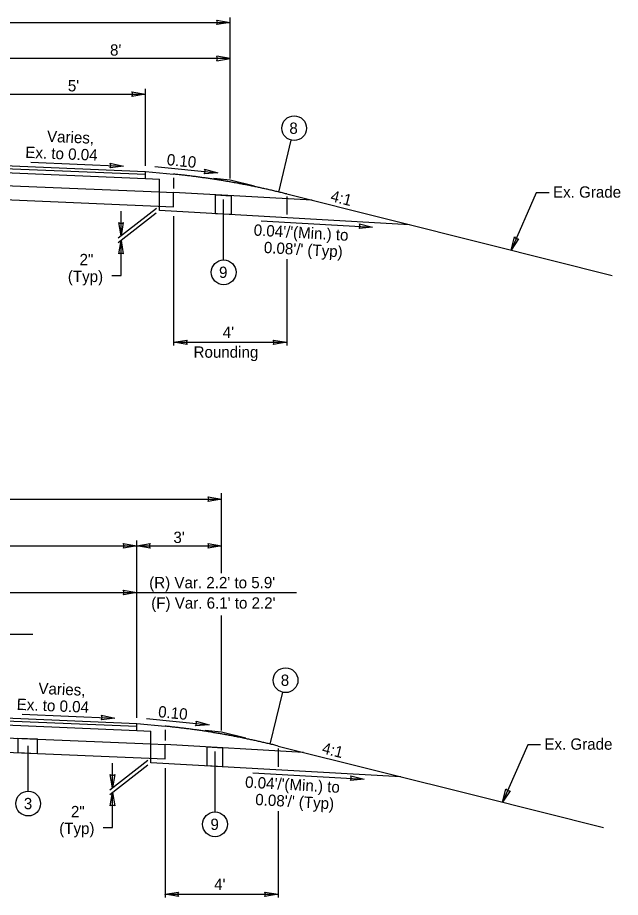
# Model space of a CAD drawing. Extents: x -219 to 803, y -225 to 180.
# Drawn here: x -126.41 to -105.09, y -38.66 to -7.57 of the extents above; entities that cross this region are included whole.
import ezdxf

# ---------------------------------------------------------------- set-up
doc = ezdxf.new("R2010")
doc.units = 0
doc.layers.add('Level 16', color=7, linetype='Continuous')
doc.layers.add('XS_X_Pavt', color=7, linetype='Continuous')

msp = doc.modelspace()

# ---------------------------------------------------------------- linework, layer by layer
at = {"layer": 'Level 16'}
for p, q in [((-137.894, -7.736), (-118.894, -7.736)), ((-119.368, -7.657), (-118.894, -7.736)), ((-118.894, -7.736), (-119.367, -7.815)), ((-118.894, -13.251), (-118.894, -7.566)), ((-119.367, -7.815), (-119.367, -7.815)), ((-118.894, -9.014), (-126.894, -9.014)), ((-119.368, -9.093), (-118.894, -9.014)), ((-118.894, -9.014), (-119.367, -8.935)), ((-119.367, -8.935), (-119.367, -8.935)), ((-122.369, -10.195), (-121.894, -10.274)), ((-121.894, -12.808), (-121.894, -10.078)), ((-126.894, -10.274), (-121.894, -10.274)), ((-121.894, -10.274), (-122.367, -10.353)), ((-122.367, -10.353), (-122.367, -10.353)), ((-117.17, -13.732), (-116.732, -11.9)), ((-125.947, -12.678), (-122.668, -12.815)), ((-123.139, -12.716), (-122.668, -12.815)), ((-126.894, -12.792), (-121.894, -13)), ((-126.894, -12.896), (-121.894, -13.104)), ((-126.892, -13.042), (-121.894, -13.25)), ((-122.668, -12.815), (-123.144, -12.874)), ((-123.144, -12.874), (-123.144, -12.874)), ((-121.894, -13.25), (-121.894, -13)), ((-121.894, -13), (-120.894, -13.1)), ((-121.554, -12.83), (-119.333, -13.052)), ((-119.333, -13.052), (-119.812, -13.084)), ((-119.798, -12.926), (-119.333, -13.052)), ((-121.894, -13.25), (-121.394, -13.271)), ((-121.394, -13.729), (-121.394, -13.271)), ((-120.894, -13.228), (-120.894, -13.603)), ((-119.812, -13.084), (-119.812, -13.084)), ((-119.469, -13.242), (-118.894, -13.3)), ((-118.894, -13.3), (-118.029, -13.516)), ((-126.889, -13.5), (-121.394, -13.729)), ((-121.394, -13.729), (-120.894, -13.75)), ((-121.394, -14.229), (-121.394, -13.729)), ((-120.894, -14.25), (-120.894, -13.75)), ((-115.997, -14.024), (-120.894, -13.75)), ((-119.124, -16.13), (-119.124, -13.992)), ((-116.894, -13.8), (-109.797, -15.574)), ((-116.894, -13.885), (-116.894, -14.531)), ((-108.066, -13.763), (-108.956, -15.784)), ((-107.615, -13.763), (-108.066, -13.763)), ((-126.886, -14), (-120.894, -14.25)), ((-121.394, -14.39), (-121.394, -14.223)), ((-121.506, -14.477), (-122.852, -15.522)), ((-121.5, -14.312), (-122.85, -15.36)), ((-122.752, -15.283), (-122.752, -14.409)), ((-112.555, -14.885), (-121.394, -14.39)), ((-120.894, -14.585), (-120.894, -19.151)), ((-122.752, -15.283), (-122.831, -14.81)), ((-122.831, -14.81), (-122.831, -14.81)), ((-122.673, -14.809), (-122.752, -15.283)), ((-117.793, -14.75), (-113.854, -14.971)), ((-114.323, -14.859), (-113.854, -14.971)), ((-113.854, -14.971), (-114.332, -15.017)), ((-114.332, -15.017), (-114.332, -15.017)), ((-122.831, -15.919), (-122.752, -15.444)), ((-122.752, -16.68), (-122.752, -15.444)), ((-122.752, -15.444), (-122.673, -15.917)), ((-108.956, -15.784), (-108.836, -15.32)), ((-108.691, -15.383), (-108.956, -15.784)), ((-108.836, -15.32), (-108.836, -15.32)), ((-109.797, -15.574), (-105.379, -16.679)), ((-122.673, -15.917), (-122.673, -15.917)), ((-116.894, -16.103), (-116.894, -19.151)), ((-123.081, -16.68), (-122.752, -16.68)), ((-120.894, -19.042), (-120.42, -18.963)), ((-120.42, -18.963), (-120.42, -18.963)), ((-117.369, -18.963), (-116.894, -19.042)), ((-120.419, -19.121), (-120.894, -19.042)), ((-120.894, -19.042), (-116.894, -19.042)), ((-116.894, -19.042), (-117.367, -19.121)), ((-117.367, -19.121), (-117.367, -19.121)), ((-119.673, -24.508), (-119.198, -24.587)), ((-119.198, -27.198), (-119.198, -24.373)), ((-138.198, -24.587), (-119.198, -24.587)), ((-119.198, -24.587), (-119.671, -24.666)), ((-119.671, -24.666), (-119.671, -24.666)), ((-122.198, -32.32), (-122.198, -26.047)), ((-138.198, -26.237), (-122.198, -26.237)), ((-122.673, -26.158), (-122.198, -26.237)), ((-122.198, -26.237), (-122.671, -26.316)), ((-122.671, -26.316), (-122.671, -26.316)), ((-122.198, -26.237), (-121.725, -26.158)), ((-121.723, -26.316), (-122.198, -26.237)), ((-122.198, -26.237), (-119.198, -26.237)), ((-121.725, -26.158), (-121.725, -26.158)), ((-119.673, -26.158), (-119.198, -26.237)), ((-119.198, -26.237), (-119.672, -26.316)), ((-119.672, -26.316), (-119.672, -26.316)), ((-127.198, -27.887), (-122.198, -27.887)), ((-122.673, -27.808), (-122.198, -27.887)), ((-122.198, -27.887), (-122.672, -27.966)), ((-122.672, -27.966), (-122.672, -27.966)), ((-122.198, -27.887), (-116.552, -27.887)), ((-119.198, -32.763), (-119.198, -28.695)), ((-126.998, -29.365), (-125.875, -29.365)), ((-117.475, -33.244), (-117.036, -31.412)), ((-127.198, -32.304), (-122.198, -32.512)), ((-126.252, -32.19), (-122.973, -32.327)), ((-122.973, -32.327), (-123.449, -32.386)), ((-123.444, -32.228), (-122.973, -32.327)), ((-127.198, -32.408), (-122.198, -32.616)), ((-127.196, -32.554), (-122.198, -32.762)), ((-123.449, -32.386), (-123.449, -32.386)), ((-122.198, -32.762), (-122.198, -32.512)), ((-122.198, -32.512), (-121.198, -32.612)), ((-121.858, -32.342), (-119.638, -32.564)), ((-119.638, -32.564), (-120.116, -32.596)), ((-120.116, -32.596), (-120.116, -32.596)), ((-120.102, -32.438), (-119.638, -32.564)), ((-122.198, -32.762), (-121.698, -32.783)), ((-121.698, -33.241), (-121.698, -32.783)), ((-121.198, -32.74), (-121.198, -33.115)), ((-119.773, -32.755), (-119.198, -32.812)), ((-119.198, -32.812), (-118.334, -33.028)), ((-127.193, -33.012), (-121.698, -33.241)), ((-125.709, -33.574), (-125.709, -33.074)), ((-121.698, -33.241), (-121.198, -33.262)), ((-121.698, -33.741), (-121.698, -33.241)), ((-121.198, -33.762), (-121.198, -33.262)), ((-116.301, -33.536), (-121.198, -33.262)), ((-127.191, -33.512), (-121.198, -33.762)), ((-126.409, -33.545), (-125.709, -33.574)), ((-126.038, -34.91), (-126.038, -33.303)), ((-119.429, -35.643), (-119.429, -33.504)), ((-117.198, -33.312), (-110.102, -35.086)), ((-117.198, -33.397), (-117.198, -34.043)), ((-108.37, -33.276), (-109.26, -35.296)), ((-107.92, -33.276), (-108.37, -33.276)), ((-121.804, -33.824), (-123.155, -34.872)), ((-121.698, -33.902), (-121.698, -33.735)), ((-121.811, -33.989), (-123.156, -35.034)), ((-123.056, -34.795), (-123.056, -33.921)), ((-112.859, -34.397), (-121.698, -33.902)), ((-121.198, -34.097), (-121.198, -38.663)), ((-123.056, -34.795), (-123.135, -34.322)), ((-123.135, -34.322), (-123.135, -34.322)), ((-122.977, -34.321), (-123.056, -34.795)), ((-118.097, -34.262), (-114.159, -34.483)), ((-114.159, -34.483), (-114.637, -34.529)), ((-114.627, -34.371), (-114.159, -34.483)), ((-114.637, -34.529), (-114.637, -34.529)), ((-123.135, -35.431), (-123.056, -34.956)), ((-123.056, -36.192), (-123.056, -34.956)), ((-123.056, -34.956), (-122.977, -35.429)), ((-110.102, -35.086), (-105.684, -36.191)), ((-109.26, -35.296), (-109.14, -34.832)), ((-108.995, -34.895), (-109.26, -35.296)), ((-109.14, -34.832), (-109.14, -34.832)), ((-122.977, -35.429), (-122.977, -35.429)), ((-117.198, -35.615), (-117.198, -38.663)), ((-123.386, -36.192), (-123.056, -36.192)), ((-121.198, -38.554), (-120.725, -38.475)), ((-120.723, -38.633), (-121.198, -38.554)), ((-121.198, -38.554), (-117.198, -38.554)), ((-120.725, -38.475), (-120.725, -38.475)), ((-117.673, -38.475), (-117.198, -38.554)), ((-117.198, -38.554), (-117.672, -38.633)), ((-117.672, -38.633), (-117.672, -38.633))]:
    msp.add_line(p, q, dxfattribs=at)
for points in [[(-119.407, -13.833), (-118.862, -13.864), (-118.862, -14.531), (-119.407, -14.501)], [(-119.711, -33.345), (-119.166, -33.376), (-119.166, -34.044), (-119.711, -34.013)]]:
    msp.add_lwpolyline(points, close=True, dxfattribs=at)
msp.add_lwpolyline([(-125.709, -33.074), (-126.409, -33.045), (-126.409, -33.545)], dxfattribs=at)
for centre in [(-116.63, -11.475), (-119.124, -16.568), (-116.934, -30.987), (-126.038, -35.347), (-119.429, -36.08)]:
    msp.add_circle(centre, 0.438, dxfattribs=at)
for centre, start, end in [((-119.488, -7.737), 327.1412, 33.822), ((-119.488, -9.013), 326.178, 32.8588), ((-122.488, -10.275), 327.1412, 33.822), ((-123.262, -12.791), 324.7553, 31.4361), ((-119.925, -12.994), 321.431, 28.1118), ((-122.753, -14.689), 237.1412, 303.822), ((-114.447, -14.931), 323.2284, 29.9091), ((-108.715, -15.241), 213.1754, 279.8561), ((-122.751, -16.038), 57.1412, 123.822), ((-120.299, -19.041), 147.1412, 213.822), ((-117.488, -19.043), 327.1412, 33.822), ((-119.793, -24.588), 327.1412, 33.822), ((-122.793, -26.238), 327.1412, 33.822), ((-121.604, -26.236), 147.1412, 213.822), ((-119.793, -26.238), 327.1412, 33.822), ((-122.793, -27.888), 327.1412, 33.822), ((-123.567, -32.303), 324.7553, 31.4361), ((-120.229, -32.506), 321.431, 28.1118), ((-123.057, -34.201), 237.1412, 303.822), ((-114.752, -34.443), 323.2284, 29.9091), ((-109.02, -34.753), 213.1754, 279.8561), ((-123.055, -35.55), 57.1412, 123.822), ((-120.604, -38.553), 147.1412, 213.822), ((-117.793, -38.555), 327.1412, 33.822)]:
    msp.add_arc(centre, 0.144, start, end, dxfattribs=at)
for points in [[(-116.894, -13.8), (-116.971, -13.781), (-117.047, -13.762), (-117.124, -13.743), (-117.201, -13.725), (-117.278, -13.707), (-117.355, -13.689), (-117.432, -13.671), (-117.509, -13.653), (-117.586, -13.636), (-117.663, -13.619), (-117.74, -13.602), (-117.817, -13.585), (-117.894, -13.569), (-117.971, -13.552), (-118.047, -13.536), (-118.124, -13.521), (-118.201, -13.505), (-118.278, -13.49), (-118.355, -13.475), (-118.432, -13.46), (-118.509, -13.445), (-118.586, -13.431), (-118.663, -13.416), (-118.74, -13.402), (-118.817, -13.389), (-118.894, -13.375), (-118.971, -13.362), (-119.047, -13.348), (-119.124, -13.336), (-119.201, -13.323), (-119.278, -13.31), (-119.355, -13.298), (-119.432, -13.286), (-119.509, -13.274), (-119.586, -13.263), (-119.663, -13.251), (-119.74, -13.24), (-119.817, -13.229), (-119.894, -13.219), (-119.971, -13.208), (-120.047, -13.198), (-120.124, -13.188), (-120.201, -13.178), (-120.278, -13.169), (-120.355, -13.159), (-120.432, -13.15), (-120.509, -13.141), (-120.586, -13.133), (-120.663, -13.124), (-120.74, -13.116), (-120.817, -13.108), (-120.894, -13.1)], [(-117.198, -33.312), (-117.275, -33.293), (-117.352, -33.274), (-117.429, -33.255), (-117.506, -33.237), (-117.583, -33.219), (-117.66, -33.201), (-117.737, -33.183), (-117.814, -33.165), (-117.89, -33.148), (-117.967, -33.131), (-118.044, -33.114), (-118.121, -33.097), (-118.198, -33.081), (-118.275, -33.065), (-118.352, -33.049), (-118.429, -33.033), (-118.506, -33.017), (-118.583, -33.002), (-118.66, -32.987), (-118.737, -32.972), (-118.814, -32.957), (-118.89, -32.943), (-118.967, -32.928), (-119.044, -32.914), (-119.121, -32.901), (-119.198, -32.887), (-119.275, -32.874), (-119.352, -32.861), (-119.429, -32.848), (-119.506, -32.835), (-119.583, -32.822), (-119.66, -32.81), (-119.737, -32.798), (-119.814, -32.786), (-119.89, -32.775), (-119.967, -32.763), (-120.044, -32.752), (-120.121, -32.741), (-120.198, -32.731), (-120.275, -32.72), (-120.352, -32.71), (-120.429, -32.7), (-120.506, -32.69), (-120.583, -32.681), (-120.66, -32.671), (-120.737, -32.662), (-120.814, -32.653), (-120.89, -32.645), (-120.967, -32.636), (-121.044, -32.628), (-121.121, -32.62), (-121.198, -32.612)]]:
    msp.add_spline(points, degree=3, dxfattribs=at)
at = {"layer": 'XS_X_Pavt'}
for points in [[(-118.897, -7.735), (-118.895, -7.736)], [(-118.896, -7.735), (-118.895, -7.736)], [(-118.897, -9.014), (-118.895, -9.013)], [(-118.896, -9.015), (-118.895, -9.013)], [(-121.897, -10.274), (-121.895, -10.275)], [(-121.896, -10.273), (-121.895, -10.275)], [(-122.672, -12.814), (-122.67, -12.815)], [(-122.671, -12.814), (-122.67, -12.815)], [(-119.336, -13.051), (-119.334, -13.052)], [(-119.336, -13.051), (-119.335, -13.052)], [(-113.858, -14.97), (-113.856, -14.971)], [(-113.857, -14.97), (-113.856, -14.971)], [(-122.753, -15.447), (-122.751, -15.445)], [(-122.751, -15.28), (-122.752, -15.282)], [(-122.751, -15.281), (-122.752, -15.282)], [(-122.752, -15.447), (-122.751, -15.446)], [(-108.954, -15.782), (-108.956, -15.783)], [(-108.954, -15.781), (-108.955, -15.783)], [(-120.891, -19.043), (-120.892, -19.042)], [(-120.89, -19.043), (-120.892, -19.042)], [(-116.897, -19.042), (-116.895, -19.043)], [(-116.896, -19.041), (-116.895, -19.043)], [(-119.202, -24.586), (-119.2, -24.587)], [(-119.201, -24.586), (-119.199, -24.587)], [(-122.202, -26.236), (-122.2, -26.237)], [(-122.201, -26.236), (-122.199, -26.237)], [(-122.196, -26.238), (-122.197, -26.237)], [(-122.195, -26.238), (-122.197, -26.237)], [(-119.202, -26.236), (-119.2, -26.237)], [(-119.201, -26.236), (-119.2, -26.237)], [(-122.202, -27.886), (-122.2, -27.887)], [(-122.201, -27.886), (-122.2, -27.887)], [(-122.976, -32.326), (-122.974, -32.327)], [(-122.975, -32.326), (-122.974, -32.327)], [(-119.641, -32.563), (-119.639, -32.564)], [(-119.64, -32.563), (-119.639, -32.564)], [(-114.162, -34.482), (-114.16, -34.483)], [(-114.162, -34.482), (-114.161, -34.483)], [(-123.056, -34.792), (-123.057, -34.794)], [(-123.055, -34.793), (-123.057, -34.794)], [(-123.057, -34.959), (-123.056, -34.957)], [(-123.057, -34.959), (-123.056, -34.958)], [(-109.258, -35.293), (-109.26, -35.295)], [(-109.259, -35.294), (-109.26, -35.295)], [(-121.196, -38.555), (-121.197, -38.554)], [(-121.195, -38.555), (-121.197, -38.554)], [(-117.202, -38.554), (-117.2, -38.555)], [(-117.201, -38.553), (-117.2, -38.555)]]:
    msp.add_lwpolyline(points, dxfattribs=at)

# ---------------------------------------------------------------- texts
at = {"layer": 'Level 16'}
for s, p in [("8'", (-123.143, -8.911)), ("5'", (-124.635, -10.174)), ('8', (-116.8, -11.675)), ('Ex. Grade', (-107.474, -13.931)), ('2"', (-124.222, -16.317)), ('9', (-119.288, -16.768)), ('(Typ)', (-124.636, -16.913)), ("4'", (-119.156, -18.888)), ('Rounding', (-120.189, -19.588)), ("3'", (-120.901, -26.137)), ("(R) Var. 2.2' to 5.9'", (-121.758, -27.736)), ("(F) Var. 6.1' to 2.2'", (-121.687, -28.456)), ('8', (-117.104, -31.187)), ('Ex. Grade', (-107.779, -33.444)), ('3', (-126.192, -35.547)), ('2"', (-124.527, -35.83)), ('(Typ)', (-124.941, -36.425)), ('9', (-119.592, -36.28)), ("4'", (-119.46, -38.4))]:
    msp.add_text(s, height=0.4, dxfattribs=at).set_placement(p)
for s, rotation, p in [('Varies,', 357.6141, (-125.379, -11.957)), ('Ex. to 0.04', 357.6141, (-126.147, -12.521)), ('0.10', 354.2898, (-121.151, -12.777)), ('4:1', 345.9638, (-115.369, -14.05)), ("0.04'/'(Min.) to", 356.7943, (-118.07, -15.269)), ("0.08'/' (Typ)", 356.7943, (-117.711, -15.885)), ('Varies,', 357.6141, (-125.684, -31.469)), ('Ex. to 0.04', 357.6141, (-126.451, -32.033)), ('0.10', 354.2898, (-121.456, -32.289)), ('4:1', 345.9638, (-115.674, -33.563)), ("0.04'/'(Min.) to", 356.7943, (-118.375, -34.781)), ("0.08'/' (Typ)", 356.7943, (-118.015, -35.397))]:
    msp.add_text(s, height=0.4, rotation=rotation, dxfattribs=at).set_placement(p)

doc.saveas('drawing.dxf')
